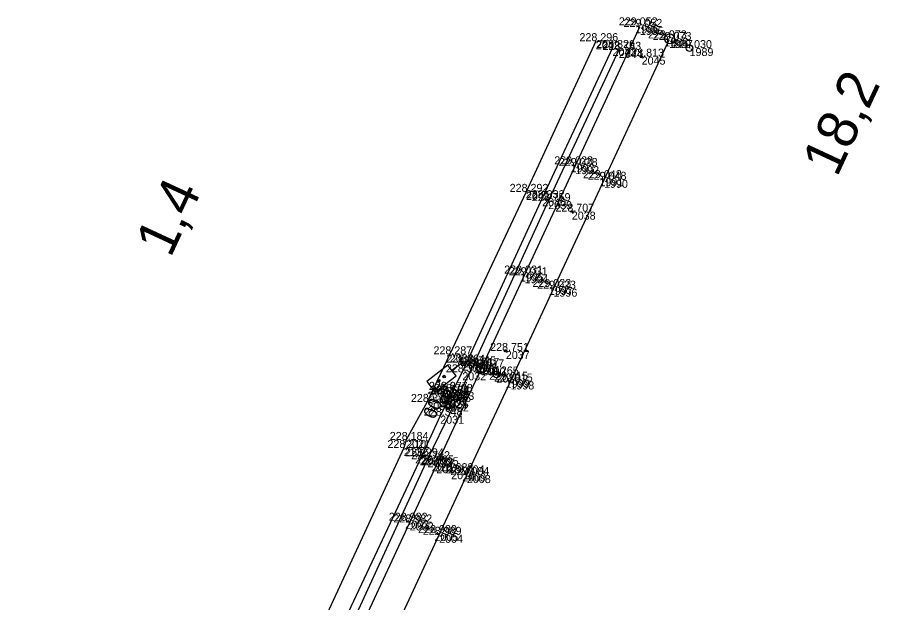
# Model space of a CAD drawing. Extents: x -644425 to -644066, y -1046154 to -1045540.
# Drawn here: x -644195 to -644065.7, y -1045627.5 to -1045539.7 of the extents above; entities that cross this region are included whole.
import ezdxf

# ---------------------------------------------------------------- set-up
doc = ezdxf.new("R2010")
doc.units = 0
for name, color, linetype in [('Vrstva 1', 7, 'Continuous'), ('Vrstva 11', 7, 'Continuous'), ('Vrstva 12', 7, 'Continuous'), ('Vrstva 23', 7, 'Continuous'), ('Vrstva 4', 7, 'Continuous'), ('Vrstva 49', 7, 'Continuous'), ('Vrstva 60', 7, 'Continuous'), ('Vrstva 61', 7, 'Continuous'), ('Vrstva 62', 7, 'Continuous'), ('Vrstva 7', 7, 'Continuous')]:
    doc.layers.add(name, color=color, linetype=linetype)

msp = doc.modelspace()

# ---------------------------------------------------------------- linework, layer by layer
at = {"layer": 'Vrstva 1'}
for points in [[(-644261.9, -1045886.22), (-644253.57, -1045868.3), (-644247.84, -1045855.91), (-644238.68, -1045836.23), (-644229.25, -1045815.94), (-644223.2, -1045802.86), (-644216.38, -1045788.16), (-644209.48, -1045773.32), (-644199.55, -1045751.95), (-644192.43, -1045736.62), (-644187.91, -1045726.87), (-644178.39, -1045706.38), (-644167.72, -1045683.41), (-644162.73, -1045672.68), (-644153.24, -1045652.21), (-644143.76, -1045631.81), (-644136.16, -1045615.44), (-644132.18, -1045606.85), (-644125.38, -1045592.19), (-644118.95, -1045578.36), (-644111.36, -1045561.99), (-644101.68, -1045541.12)], [(-644257.58, -1045888.2), (-644249.37, -1045870.52), (-644243.12, -1045857.07), (-644234.39, -1045838.24), (-644224.95, -1045817.93), (-644218.68, -1045804.41), (-644212.07, -1045790.2), (-644205.18, -1045775.37), (-644195.28, -1045754.06), (-644188.04, -1045738.48), (-644183.51, -1045728.69), (-644173.98, -1045708.19), (-644163.21, -1045685.03), (-644158.47, -1045674.84), (-644148.94, -1045654.32), (-644139.46, -1045633.91), (-644131.76, -1045617.29), (-644127.6, -1045608.33), (-644121.08, -1045594.3), (-644114.62, -1045580.38), (-644107.04, -1045564.05), (-644097.3, -1045543.08)]]:
    msp.add_lwpolyline(points, dxfattribs=at)
at = {"layer": 'Vrstva 11'}
for p, q in [((-644130.7, -1045596.61), (-644131.01, -1045595.75)), ((-644130.34, -1045596.49), (-644130.66, -1045595.62)), ((-644131.12, -1045597.53), (-644131.44, -1045596.67)), ((-644130.77, -1045597.41), (-644131.09, -1045596.54))]:
    msp.add_line(p, q, dxfattribs=at)
for centre in [(-644130.67, -1045596.11), (-644131.1, -1045597.04)]:
    msp.add_circle(centre, 0.5, dxfattribs=at)
at = {"layer": 'Vrstva 12'}
for p, q in [((-644131.62, -1045597.24), (-644130.84, -1045595.56)), ((-644130.84, -1045595.55), (-644130.07, -1045595.86))]:
    msp.add_line(p, q, dxfattribs=at)
msp.add_lwpolyline([(-644130.87, -1045597.59), (-644131.62, -1045597.24), (-644131.62, -1045597.23), (-644130.87, -1045597.59), (-644130.07, -1045595.86), (-644130.84, -1045595.56), (-644130.84, -1045595.55), (-644131.62, -1045597.23)], dxfattribs=at)
at = {"layer": 'Vrstva 23'}
for p, q in [((-644130.56, -1045596.18), (-644130.56, -1045596.18)), ((-644130.99, -1045597.11), (-644130.99, -1045597.11))]:
    msp.add_line(p, q, dxfattribs=at)
at = {"layer": 'Vrstva 4'}
for points in [[(-644104.83, -1045544.56), (-644115.41, -1045567.25), (-644126.59, -1045591.73), (-644133.49, -1045605.95), (-644145.84, -1045632.82), (-644153.92, -1045650.61), (-644164.19, -1045672.05), (-644168.98, -1045682.75), (-644179.4, -1045705.41), (-644189.24, -1045726.17), (-644192.71, -1045732.79), (-644195.84, -1045739.43), (-644200.88, -1045751.59), (-644210.7, -1045773.33), (-644219.76, -1045791.51), (-644230.98, -1045815.66), (-644240.43, -1045836.08), (-644246.86, -1045849.97)], [(-644105.77, -1045544.28), (-644116.32, -1045566.81), (-644128.29, -1045592.92), (-644131.6, -1045599.43), (-644134.41, -1045605.52), (-644146.95, -1045632.25), (-644154.56, -1045649.59), (-644165.04, -1045671.65), (-644170.05, -1045682.44), (-644180.47, -1045704.85), (-644190.28, -1045725.94), (-644192.66, -1045731.19), (-644192.71, -1045732.79)]]:
    msp.add_lwpolyline(points, dxfattribs=at)
at = {"layer": 'Vrstva 49'}
for p, q in [((-644101.32, -1045545.81), (-644101.49, -1045545.34)), ((-644101.64, -1045545.66), (-644101.17, -1045545.49)), ((-644111.97, -1045568.6), (-644111.8, -1045569.07)), ((-644111.65, -1045568.75), (-644112.12, -1045568.92)), ((-644122, -1045589.81), (-644121.53, -1045589.64)), ((-644121.68, -1045589.96), (-644121.85, -1045589.49)), ((-644129.73, -1045607.66), (-644130.2, -1045607.83)), ((-644130.05, -1045607.51), (-644129.88, -1045607.98))]:
    msp.add_line(p, q, dxfattribs=at)
msp.add_lwpolyline([(-644108.28, -1045543.26), (-644118.74, -1045565.86), (-644130.16, -1045590.22), (-644133.54, -1045597.37), (-644136.71, -1045603.06), (-644137.06, -1045604.26), (-644149.2, -1045630.48), (-644158.17, -1045649.72), (-644167.87, -1045670.55), (-644172.45, -1045681.19), (-644183.45, -1045704.16), (-644187.35, -1045711.69), (-644187.99, -1045715.93), (-644193.41, -1045727.71), (-644193.47, -1045732.31)], dxfattribs=at)
at = {"layer": 'Vrstva 60'}
for p, q in [((-644102.38, -1045540.89), (-644102.38, -1045540.89)), ((-644101.68, -1045541.12), (-644101.68, -1045541.12)), ((-644108.28, -1045543.26), (-644108.28, -1045543.26)), ((-644098.01, -1045542.84), (-644098.01, -1045542.84)), ((-644097.3, -1045543.08), (-644097.3, -1045543.08)), ((-644105.77, -1045544.28), (-644105.77, -1045544.28)), ((-644104.83, -1045544.56), (-644104.83, -1045544.56)), ((-644094.23, -1045544.3), (-644094.23, -1045544.3)), ((-644101.41, -1045545.58), (-644101.41, -1045545.58)), ((-644112.06, -1045561.73), (-644112.06, -1045561.73)), ((-644111.36, -1045561.99), (-644111.36, -1045561.99)), ((-644107.74, -1045563.81), (-644107.74, -1045563.81)), ((-644107.04, -1045564.05), (-644107.04, -1045564.05)), ((-644118.74, -1045565.86), (-644118.74, -1045565.86)), ((-644116.32, -1045566.81), (-644116.32, -1045566.81)), ((-644115.41, -1045567.25), (-644115.41, -1045567.25)), ((-644111.88, -1045568.83), (-644111.88, -1045568.83)), ((-644119.66, -1045578.11), (-644119.66, -1045578.11)), ((-644118.95, -1045578.36), (-644118.95, -1045578.36)), ((-644115.33, -1045580.12), (-644115.33, -1045580.12)), ((-644114.62, -1045580.38), (-644114.62, -1045580.38)), ((-644130.16, -1045590.22), (-644130.16, -1045590.22)), ((-644121.77, -1045589.72), (-644121.77, -1045589.72)), ((-644128.24, -1045591.46), (-644128.24, -1045591.46)), ((-644126.59, -1045591.73), (-644126.59, -1045591.73)), ((-644128.29, -1045592.92), (-644128.29, -1045592.92)), ((-644126.09, -1045591.95), (-644126.09, -1045591.95)), ((-644125.38, -1045592.19), (-644125.38, -1045592.19)), ((-644123.18, -1045593.25), (-644123.18, -1045593.25)), ((-644121.79, -1045594.04), (-644121.79, -1045594.04)), ((-644121.08, -1045594.3), (-644121.08, -1045594.3)), ((-644130.84, -1045595.55), (-644130.84, -1045595.55)), ((-644130.84, -1045595.56), (-644130.84, -1045595.56)), ((-644131.1, -1045597.04), (-644131.1, -1045597.04)), ((-644130.67, -1045596.11), (-644130.67, -1045596.11)), ((-644130.07, -1045595.86), (-644130.07, -1045595.86)), ((-644133.54, -1045597.37), (-644133.54, -1045597.37)), ((-644131.62, -1045597.23), (-644131.62, -1045597.23)), ((-644131.62, -1045597.24), (-644131.62, -1045597.24)), ((-644130.87, -1045597.59), (-644130.87, -1045597.59)), ((-644131.6, -1045599.43), (-644131.6, -1045599.43)), ((-644136.71, -1045603.06), (-644136.71, -1045603.06)), ((-644137.06, -1045604.26), (-644137.06, -1045604.26)), ((-644134.41, -1045605.52), (-644134.41, -1045605.52)), ((-644133.49, -1045605.95), (-644133.49, -1045605.95)), ((-644132.88, -1045606.59), (-644132.88, -1045606.59)), ((-644132.18, -1045606.85), (-644132.18, -1045606.85)), ((-644129.96, -1045607.75), (-644129.96, -1045607.75)), ((-644128.3, -1045608.08), (-644128.3, -1045608.08)), ((-644127.6, -1045608.33), (-644127.6, -1045608.33)), ((-644136.85, -1045615.18), (-644136.85, -1045615.18)), ((-644136.16, -1045615.44), (-644136.16, -1045615.44)), ((-644132.46, -1045617.03), (-644132.46, -1045617.03)), ((-644131.76, -1045617.29), (-644131.76, -1045617.29))]:
    msp.add_line(p, q, dxfattribs=at)
at = {"layer": 'Vrstva 62'}
for p, q in [((-644102.38, -1045540.89), (-644102.38, -1045540.89)), ((-644098.01, -1045542.84), (-644098.01, -1045542.84)), ((-644112.06, -1045561.73), (-644112.06, -1045561.73)), ((-644107.74, -1045563.81), (-644107.74, -1045563.81)), ((-644119.66, -1045578.11), (-644119.66, -1045578.11)), ((-644115.33, -1045580.12), (-644115.33, -1045580.12)), ((-644126.09, -1045591.95), (-644126.09, -1045591.95)), ((-644121.79, -1045594.04), (-644121.79, -1045594.04)), ((-644132.88, -1045606.59), (-644132.88, -1045606.59)), ((-644128.3, -1045608.08), (-644128.3, -1045608.08)), ((-644136.85, -1045615.18), (-644136.85, -1045615.18)), ((-644132.46, -1045617.03), (-644132.46, -1045617.03))]:
    msp.add_line(p, q, dxfattribs=at)
at = {"layer": 'Vrstva 7'}
for p, q in [((-644094.21, -1045544.25), (-644094.25, -1045544.34)), ((-644127.79, -1045592.06), (-644128.69, -1045590.86)), ((-644123.16, -1045593.21), (-644123.21, -1045593.3)), ((-644132.02, -1045594.15), (-644131.63, -1045594.2)), ((-644131.23, -1045593.55), (-644130.83, -1045593.61))]:
    msp.add_line(p, q, dxfattribs=at)
msp.add_lwpolyline([(-644128.24, -1045591.46), (-644129.84, -1045592.67), (-644130.44, -1045591.87), (-644133.63, -1045594.28), (-644132.42, -1045595.88), (-644129.23, -1045593.46), (-644129.84, -1045592.67)], dxfattribs=at)
for centre, radius in [((-644097.22, -1045542.9), 0.75), ((-644094.23, -1045544.3), 0.5), ((-644125.4, -1045592.23), 0.75), ((-644123.18, -1045593.25), 0.5), ((-644131.83, -1045594.18), 0.2), ((-644131.03, -1045593.57), 0.2)]:
    msp.add_circle(centre, radius, dxfattribs=at)

# ---------------------------------------------------------------- texts
at = {"layer": 'Vrstva 11'}
msp.add_text('60', height=2, rotation=65.1099, dxfattribs=at).set_placement((-644132.47, -1045600.11))
at = {"layer": 'Vrstva 60'}
for s, p in [('1986', (-644102.38, -1045542.09)), ('1985', (-644101.68, -1045542.32)), ('2042', (-644108.28, -1045544.46)), ('1988', (-644098.01, -1045544.04)), ('1987', (-644097.3, -1045544.28)), ('2043', (-644105.77, -1045545.48)), ('2044', (-644104.83, -1045545.76)), ('1989', (-644094.23, -1045545.49)), ('2045', (-644101.41, -1045546.78)), ('1993', (-644112.06, -1045562.93)), ('1992', (-644111.36, -1045563.2)), ('1991', (-644107.74, -1045565.01)), ('1990', (-644107.04, -1045565.25)), ('2041', (-644118.74, -1045567.06)), ('2040', (-644116.32, -1045568.01)), ('2039', (-644115.41, -1045568.45)), ('2038', (-644111.88, -1045570.03)), ('1995', (-644119.66, -1045579.31)), ('1994', (-644118.95, -1045579.56)), ('1997', (-644115.33, -1045581.32)), ('1996', (-644114.62, -1045581.58)), ('2033', (-644130.16, -1045591.42)), ('2037', (-644121.77, -1045590.92)), ('2034', (-644128.24, -1045592.66)), ('2035', (-644126.59, -1045592.93)), ('2001', (-644126.09, -1045593.15)), ('2032', (-644128.29, -1045594.12)), ('2000', (-644125.38, -1045593.39)), ('2036', (-644123.18, -1045594.45)), ('1999', (-644121.79, -1045595.24)), ('1998', (-644121.08, -1045595.49)), ('2028', (-644130.84, -1045596.76)), ('2029', (-644130.84, -1045596.75)), ('2024', (-644131.1, -1045598.24)), ('2025', (-644130.99, -1045598.31)), ('2027', (-644130.67, -1045597.31)), ('2026', (-644130.56, -1045597.38)), ('2023', (-644130.07, -1045597.06)), ('2030', (-644133.54, -1045598.57)), ('41', (-644131.62, -1045598.44)), ('40', (-644131.62, -1045598.43)), ('2022', (-644130.87, -1045598.79)), ('2031', (-644131.6, -1045600.63)), ('2021', (-644136.71, -1045604.26)), ('2132', (-644137.06, -1045605.46)), ('2020', (-644134.41, -1045606.72)), ('2019', (-644133.49, -1045607.15)), ('2017', (-644132.88, -1045607.79)), ('2016', (-644132.18, -1045608.05)), ('2018', (-644129.96, -1045608.95)), ('2009', (-644128.3, -1045609.28)), ('2008', (-644127.6, -1045609.53)), ('2003', (-644136.85, -1045616.38)), ('2002', (-644136.16, -1045616.64)), ('2005', (-644132.46, -1045618.23)), ('2004', (-644131.76, -1045618.49))]:
    msp.add_text(s, height=1.2, dxfattribs=at).set_placement(p)
at = {"layer": 'Vrstva 61'}
for s, p in [('229.052', (-644104.83, -1045540.89)), ('229.052', (-644104.13, -1045541.12)), ('228.296', (-644110.73, -1045543.26)), ('229.073', (-644100.46, -1045542.84)), ('229.073', (-644099.75, -1045543.08)), ('228.326', (-644108.22, -1045544.28)), ('228.783', (-644107.29, -1045544.56)), ('229.030', (-644096.68, -1045544.3)), ('228.813', (-644103.86, -1045545.58)), ('229.028', (-644114.51, -1045561.73)), ('229.028', (-644113.82, -1045561.99)), ('229.048', (-644110.19, -1045563.81)), ('229.048', (-644109.49, -1045564.05)), ('228.292', (-644121.19, -1045565.86)), ('228.332', (-644118.77, -1045566.81)), ('228.759', (-644117.87, -1045567.25)), ('228.707', (-644114.33, -1045568.83)), ('229.031', (-644122.01, -1045578.11)), ('229.031', (-644121.31, -1045578.36)), ('229.023', (-644117.78, -1045580.12)), ('229.023', (-644117.07, -1045580.38)), ('228.287', (-644132.61, -1045590.22)), ('228.751', (-644124.12, -1045589.72)), ('228.264', (-644130.69, -1045591.46)), ('228.745', (-644129.04, -1045591.73)), ('228.335', (-644130.75, -1045592.92)), ('229.017', (-644128.55, -1045591.95)), ('229.017', (-644127.83, -1045592.19)), ('229.265', (-644125.64, -1045593.25)), ('229.015', (-644124.25, -1045594.04)), ('229.015', (-644123.54, -1045594.3)), ('228.677', (-644133.3, -1045595.56)), ('228.277', (-644133.29, -1045595.55)), ('228.684', (-644133.12, -1045596.11)), ('228.684', (-644133.01, -1045596.18)), ('228.708', (-644132.52, -1045595.86)), ('228.249', (-644135.99, -1045597.37)), ('228.260', (-644134.07, -1045597.23)), ('228.660', (-644134.07, -1045597.24)), ('228.688', (-644133.55, -1045597.04)), ('228.687', (-644133.44, -1045597.11)), ('228.690', (-644133.32, -1045597.59)), ('228.348', (-644134.06, -1045599.43)), ('228.184', (-644139.16, -1045603.06)), ('228.210', (-644139.51, -1045604.26)), ('228.294', (-644136.86, -1045605.52)), ('228.742', (-644135.94, -1045605.95)), ('228.995', (-644135.34, -1045606.59)), ('228.995', (-644134.64, -1045606.85)), ('228.688', (-644132.42, -1045607.75)), ('229.004', (-644130.75, -1045608.08)), ('229.004', (-644130.05, -1045608.33)), ('228.982', (-644139.3, -1045615.18)), ('228.982', (-644138.61, -1045615.44)), ('228.989', (-644134.91, -1045617.03)), ('228.989', (-644134.21, -1045617.29))]:
    msp.add_text(s, height=1.2, dxfattribs=at).set_placement(p)
at = {"layer": 'Vrstva 7'}
for s, rotation, p in [('18,2', 65.0341, (-644072.15, -1045563.79)), ('1,4', 65.1099, (-644172.03, -1045575.87))]:
    msp.add_text(s, height=6, rotation=rotation, dxfattribs=at).set_placement(p)

doc.saveas('drawing.dxf')
